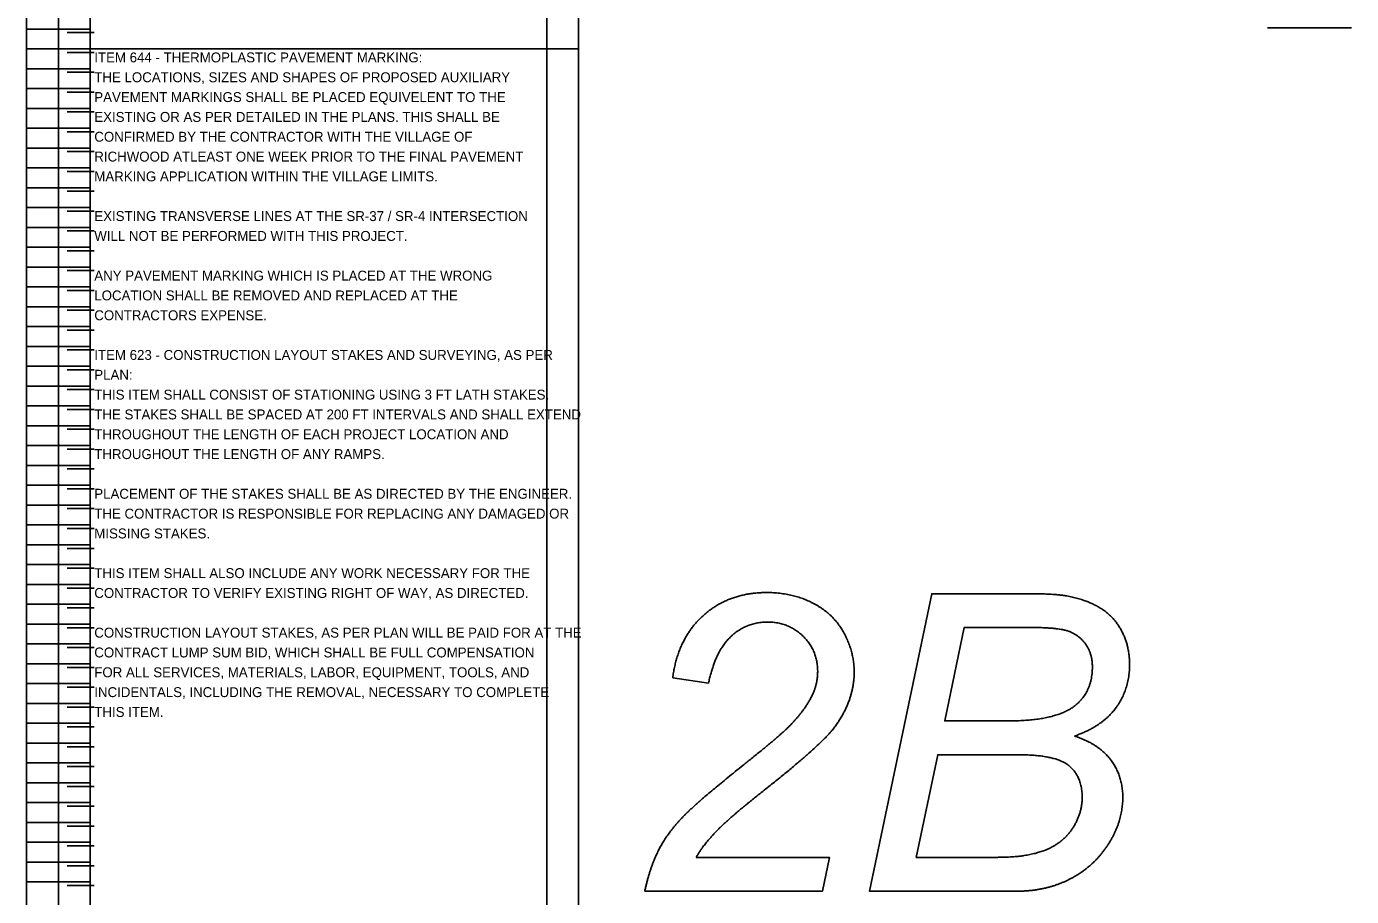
# Model space of a CAD drawing. Extents: x 12316 to 12541, y 1124 to 1850.
# Drawn here: x 12521.92 to 12540.62, y 1737.03 to 1749.31 of the extents above; entities that cross this region are included whole.
import ezdxf

# ---------------------------------------------------------------- set-up
doc = ezdxf.new("R2010")
doc.units = 0
for name, color, linetype in [('SC_Scratch1', 7, 'Continuous'), ('SH_Data', 7, 'Continuous'), ('SH_Text', 7, 'Continuous')]:
    doc.layers.add(name, color=color, linetype=linetype)

msp = doc.modelspace()

# ---------------------------------------------------------------- linework, layer by layer
at = {"layer": 'SC_Scratch1'}
for p, q in [((12522.819, 1769.381), (12522.819, 1728.831)), ((12521.919, 1748.991), (12521.919, 1769.151)), ((12522.819, 1748.991), (12522.819, 1769.151)), ((12521.919, 1749.271), (12522.819, 1749.271)), ((12522.876, 1749.221), (12522.492, 1749.221)), ((12521.919, 1748.991), (12522.819, 1748.991)), ((12521.919, 1728.831), (12521.919, 1748.991)), ((12521.919, 1748.991), (12522.819, 1748.991)), ((12522.876, 1748.941), (12522.492, 1748.941)), ((12522.819, 1728.831), (12522.819, 1748.991)), ((12521.919, 1748.711), (12522.819, 1748.711)), ((12522.876, 1748.661), (12522.492, 1748.661)), ((12521.919, 1748.431), (12522.819, 1748.431)), ((12522.876, 1748.381), (12522.492, 1748.381)), ((12521.919, 1748.151), (12522.819, 1748.151)), ((12522.876, 1748.101), (12522.492, 1748.101)), ((12521.919, 1747.871), (12522.819, 1747.871)), ((12522.876, 1747.821), (12522.492, 1747.821)), ((12521.919, 1747.591), (12522.819, 1747.591)), ((12522.876, 1747.541), (12522.492, 1747.541)), ((12521.919, 1747.311), (12522.819, 1747.311)), ((12522.876, 1747.261), (12522.492, 1747.261)), ((12521.919, 1747.031), (12522.819, 1747.031)), ((12522.876, 1746.981), (12522.492, 1746.981)), ((12521.919, 1746.751), (12522.819, 1746.751)), ((12522.876, 1746.701), (12522.492, 1746.701)), ((12521.919, 1746.471), (12522.819, 1746.471)), ((12522.876, 1746.421), (12522.492, 1746.421)), ((12521.919, 1746.191), (12522.819, 1746.191)), ((12522.876, 1746.141), (12522.492, 1746.141)), ((12521.919, 1745.911), (12522.819, 1745.911)), ((12522.876, 1745.861), (12522.492, 1745.861)), ((12521.919, 1745.631), (12522.819, 1745.631)), ((12522.876, 1745.581), (12522.492, 1745.581)), ((12521.919, 1745.351), (12522.819, 1745.351)), ((12522.876, 1745.301), (12522.492, 1745.301)), ((12521.919, 1745.071), (12522.819, 1745.071)), ((12522.876, 1745.021), (12522.492, 1745.021)), ((12521.919, 1744.791), (12522.819, 1744.791)), ((12522.876, 1744.741), (12522.492, 1744.741)), ((12521.919, 1744.511), (12522.819, 1744.511)), ((12522.876, 1744.461), (12522.492, 1744.461)), ((12521.919, 1744.231), (12522.819, 1744.231)), ((12522.876, 1744.181), (12522.492, 1744.181)), ((12521.919, 1743.951), (12522.819, 1743.951)), ((12522.876, 1743.901), (12522.492, 1743.901)), ((12521.919, 1743.671), (12522.819, 1743.671)), ((12522.876, 1743.621), (12522.492, 1743.621)), ((12521.919, 1743.391), (12522.819, 1743.391)), ((12522.876, 1743.341), (12522.492, 1743.341)), ((12521.919, 1743.111), (12522.819, 1743.111)), ((12522.876, 1743.061), (12522.492, 1743.061)), ((12521.919, 1742.831), (12522.819, 1742.831)), ((12522.876, 1742.781), (12522.492, 1742.781)), ((12521.919, 1742.551), (12522.819, 1742.551)), ((12522.876, 1742.501), (12522.492, 1742.501)), ((12521.919, 1742.271), (12522.819, 1742.271)), ((12522.876, 1742.221), (12522.492, 1742.221)), ((12521.919, 1741.991), (12522.819, 1741.991)), ((12522.876, 1741.941), (12522.492, 1741.941)), ((12521.919, 1741.711), (12522.819, 1741.711)), ((12522.876, 1741.661), (12522.492, 1741.661)), ((12521.919, 1741.431), (12522.819, 1741.431)), ((12522.876, 1741.381), (12522.492, 1741.381)), ((12521.919, 1741.151), (12522.819, 1741.151)), ((12522.876, 1741.101), (12522.492, 1741.101)), ((12521.919, 1740.871), (12522.819, 1740.871)), ((12522.876, 1740.821), (12522.492, 1740.821)), ((12521.919, 1740.591), (12522.819, 1740.591)), ((12522.876, 1740.541), (12522.492, 1740.541)), ((12521.919, 1740.311), (12522.819, 1740.311)), ((12522.876, 1740.261), (12522.492, 1740.261)), ((12521.919, 1740.031), (12522.819, 1740.031)), ((12531.543, 1740.039), (12531.037, 1740.114)), ((12522.876, 1739.981), (12522.492, 1739.981)), ((12521.919, 1739.751), (12522.819, 1739.751)), ((12522.876, 1739.701), (12522.492, 1739.701)), ((12521.919, 1739.471), (12522.819, 1739.471)), ((12522.876, 1739.421), (12522.492, 1739.421)), ((12521.919, 1739.191), (12522.819, 1739.191)), ((12522.876, 1739.141), (12522.492, 1739.141)), ((12521.919, 1738.911), (12522.819, 1738.911)), ((12522.876, 1738.861), (12522.492, 1738.861)), ((12521.919, 1738.631), (12522.819, 1738.631)), ((12522.876, 1738.581), (12522.492, 1738.581)), ((12521.919, 1738.351), (12522.819, 1738.351)), ((12522.876, 1738.301), (12522.492, 1738.301)), ((12521.919, 1738.071), (12522.819, 1738.071)), ((12522.876, 1738.021), (12522.492, 1738.021)), ((12521.919, 1737.791), (12522.819, 1737.791)), ((12522.876, 1737.741), (12522.492, 1737.741)), ((12521.919, 1737.511), (12522.819, 1737.511)), ((12522.876, 1737.461), (12522.492, 1737.461)), ((12521.919, 1737.231), (12522.819, 1737.231)), ((12522.876, 1737.181), (12522.492, 1737.181))]:
    msp.add_line(p, q, dxfattribs=at)
for points in [[(12522.369, 1769.151), (12529.709, 1769.151), (12529.709, 1748.991), (12522.369, 1748.991)], [(12522.819, 1769.151), (12529.259, 1769.151), (12529.259, 1748.991), (12522.819, 1748.991)], [(12522.369, 1748.991), (12529.709, 1748.991), (12529.709, 1728.831), (12522.369, 1728.831)], [(12522.819, 1748.991), (12529.259, 1748.991), (12529.259, 1728.831), (12522.819, 1728.831)]]:
    msp.add_lwpolyline(points, close=True, dxfattribs=at)
for points in [[(12536.034, 1741.301), (12534.693, 1741.301), (12533.816, 1737.101), (12535.897, 1737.101)], [(12535.771, 1739.505), (12534.877, 1739.505), (12535.152, 1740.824), (12536.09, 1740.824)], [(12535.467, 1737.578), (12534.474, 1737.578), (12534.777, 1739.028), (12535.893, 1739.028)], [(12531.369, 1737.578), (12533.249, 1737.578), (12533.149, 1737.101), (12530.643, 1737.101)]]:
    msp.add_lwpolyline(points, dxfattribs=at)
for points in [[(12531.471, 1740.995), (12531.831, 1741.317), (12532.366, 1741.317)], [(12532.366, 1741.317), (12532.724, 1741.317), (12533.015, 1741.168)], [(12533.015, 1741.168), (12533.306, 1741.019), (12533.452, 1740.75)], [(12536.577, 1741.272), (12536.4, 1741.301), (12536.034, 1741.301)], [(12537.066, 1741.101), (12536.867, 1741.223), (12536.577, 1741.272)], [(12531.037, 1740.114), (12531.111, 1740.672), (12531.471, 1740.995)], [(12537.375, 1740.769), (12537.266, 1740.98), (12537.066, 1741.101)], [(12532.374, 1740.901), (12532.079, 1740.901), (12531.858, 1740.696)], [(12532.878, 1740.699), (12532.673, 1740.901), (12532.374, 1740.901)], [(12536.09, 1740.824), (12536.493, 1740.824), (12536.639, 1740.765)], [(12531.858, 1740.696), (12531.637, 1740.491), (12531.543, 1740.039)], [(12533.083, 1740.208), (12533.083, 1740.497), (12532.878, 1740.699)], [(12533.452, 1740.75), (12533.598, 1740.481), (12533.598, 1740.194)], [(12536.639, 1740.765), (12536.785, 1740.706), (12536.872, 1740.577)], [(12537.484, 1740.303), (12537.484, 1740.558), (12537.375, 1740.769)], [(12536.872, 1740.577), (12536.959, 1740.447), (12536.959, 1740.269)], [(12536.959, 1740.269), (12536.959, 1739.896), (12536.686, 1739.7)], [(12537.293, 1739.692), (12537.484, 1739.956), (12537.484, 1740.303)], [(12533.017, 1739.89), (12533.083, 1740.036), (12533.083, 1740.208)], [(12533.598, 1740.194), (12533.598, 1739.776), (12533.3, 1739.389)], [(12532.704, 1739.452), (12532.919, 1739.676), (12533.017, 1739.89)], [(12536.686, 1739.7), (12536.413, 1739.505), (12535.771, 1739.505)], [(12536.707, 1739.291), (12537.101, 1739.428), (12537.293, 1739.692)], [(12532.148, 1738.974), (12532.555, 1739.298), (12532.704, 1739.452)], [(12533.3, 1739.389), (12533.117, 1739.149), (12532.223, 1738.442)], [(12537.219, 1738.954), (12537.049, 1739.179), (12536.707, 1739.291)], [(12531.242, 1738.211), (12531.477, 1738.439), (12532.148, 1738.974)], [(12535.893, 1739.028), (12536.437, 1739.028), (12536.626, 1738.875)], [(12537.388, 1738.429), (12537.388, 1738.73), (12537.219, 1738.954)], [(12536.626, 1738.875), (12536.815, 1738.722), (12536.815, 1738.427)], [(12532.223, 1738.442), (12531.839, 1738.139), (12531.651, 1737.944)], [(12536.815, 1738.427), (12536.815, 1738.23), (12536.717, 1738.05)], [(12537.185, 1737.765), (12537.388, 1738.083), (12537.388, 1738.429)], [(12530.865, 1737.73), (12531.007, 1737.984), (12531.242, 1738.211)], [(12536.717, 1738.05), (12536.619, 1737.87), (12536.447, 1737.759)], [(12531.651, 1737.944), (12531.463, 1737.75), (12531.369, 1737.578)], [(12530.643, 1737.101), (12530.724, 1737.476), (12530.865, 1737.73)], [(12535.998, 1737.604), (12535.862, 1737.578), (12535.467, 1737.578)], [(12536.447, 1737.759), (12536.275, 1737.649), (12535.998, 1737.604)], [(12536.645, 1737.274), (12536.981, 1737.447), (12537.185, 1737.765)], [(12535.897, 1737.101), (12536.31, 1737.101), (12536.645, 1737.274)]]:
    msp.add_open_spline(points, degree=2, dxfattribs=at)
at = {"layer": 'SH_Text'}
msp.add_line((12539.432, 1749.287), (12540.615, 1749.287), dxfattribs=at)

# ---------------------------------------------------------------- texts
at = {"layer": 'SH_Data'}
for s, p in [('ITEM 623 - CONSTRUCTION LAYOUT STAKES AND SURVEYING, AS PER ', (12522.876, 1744.601)), ('PLAN:', (12522.876, 1744.321)), ('THIS ITEM SHALL CONSIST OF STATIONING USING 3 FT LATH STAKES. ', (12522.876, 1744.041)), ('THE STAKES SHALL BE SPACED AT 200 FT INTERVALS AND SHALL EXTEND ', (12522.876, 1743.761)), ('THROUGHOUT THE LENGTH OF EACH PROJECT LOCATION AND ', (12522.876, 1743.481)), ('THROUGHOUT THE LENGTH OF ANY RAMPS. ', (12522.876, 1743.201)), ('PLACEMENT OF THE STAKES SHALL BE AS DIRECTED BY THE ENGINEER. ', (12522.876, 1742.641)), ('THE CONTRACTOR IS RESPONSIBLE FOR REPLACING ANY DAMAGED OR ', (12522.876, 1742.361)), ('MISSING STAKES.', (12522.876, 1742.081)), ('THIS ITEM SHALL ALSO INCLUDE ANY WORK NECESSARY FOR THE ', (12522.876, 1741.521)), ('CONTRACTOR TO VERIFY EXISTING RIGHT OF WAY, AS DIRECTED.', (12522.876, 1741.241)), ('CONSTRUCTION LAYOUT STAKES, AS PER PLAN WILL BE PAID FOR AT THE ', (12522.876, 1740.681)), ('CONTRACT LUMP SUM BID, WHICH SHALL BE FULL COMPENSATION  ', (12522.876, 1740.401)), ('FOR ALL SERVICES, MATERIALS, LABOR, EQUIPMENT, TOOLS, AND ', (12522.876, 1740.121)), ('INCIDENTALS, INCLUDING THE REMOVAL, NECESSARY TO COMPLETE ', (12522.876, 1739.841)), ('THIS ITEM.', (12522.876, 1739.561))]:
    msp.add_text(s, height=0.14, dxfattribs=at).set_placement(p)
at = {"layer": 'SH_Text'}
for s, p in [('ITEM 644 - THERMOPLASTIC PAVEMENT MARKING:', (12522.876, 1748.801)), ('THE LOCATIONS, SIZES AND SHAPES OF PROPOSED AUXILIARY ', (12522.876, 1748.521)), ('PAVEMENT MARKINGS SHALL BE PLACED EQUIVELENT TO THE ', (12522.876, 1748.241)), ('EXISTING OR AS PER DETAILED IN THE PLANS. THIS SHALL BE ', (12522.876, 1747.961)), ('CONFIRMED BY THE CONTRACTOR WITH THE VILLAGE OF ', (12522.876, 1747.681)), ('RICHWOOD ATLEAST ONE WEEK PRIOR TO THE FINAL PAVEMENT ', (12522.876, 1747.401)), ('MARKING APPLICATION WITHIN THE VILLAGE LIMITS.  ', (12522.876, 1747.121)), ('EXISTING TRANSVERSE LINES AT THE SR-37 / SR-4 INTERSECTION ', (12522.876, 1746.561)), ('WILL NOT BE PERFORMED WITH THIS PROJECT.', (12522.876, 1746.281)), ('ANY PAVEMENT MARKING WHICH IS PLACED AT THE WRONG ', (12522.876, 1745.721)), ('LOCATION SHALL BE REMOVED AND REPLACED AT THE ', (12522.876, 1745.441)), ('CONTRACTORS EXPENSE. ', (12522.876, 1745.161))]:
    msp.add_text(s, height=0.14, dxfattribs=at).set_placement(p)

doc.saveas('drawing.dxf')
